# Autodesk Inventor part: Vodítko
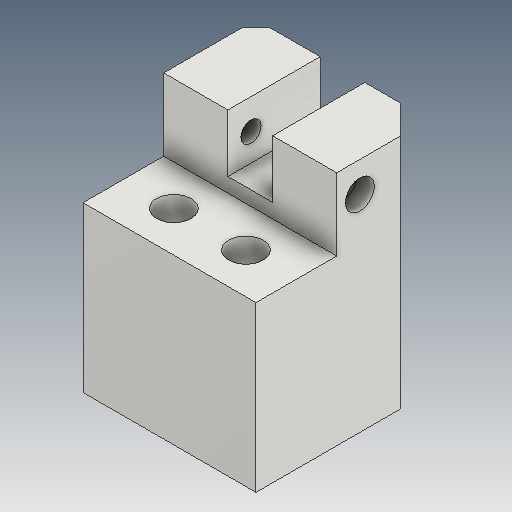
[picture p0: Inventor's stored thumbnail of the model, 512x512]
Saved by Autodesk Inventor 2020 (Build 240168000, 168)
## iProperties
Created: 2025-03
Part Number: Vodítko
Material: Ocel
Document SubType Name: Modeling
Designer: doma
Density: 7.85 g/cm^3
Appearance: Ocel
Mass: 1726.6 g
Surface Area: 323.089 cm^2
Volume: 219.949 cm^3
Author: doma
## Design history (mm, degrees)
sketch "Náčrt1"
  geometry: L1 (0, 0)-(60, 0); L2 (60, 0)-(60, 82); L3 (0, 82)-(0, 0); L4 (30, 62)-(37.75, 62); L5 (30, 62)-(22.25, 62); L6 (22.25, 62)-(22.25, 82); L7 (37.75, 62)-(37.75, 82); L8 (60, 82)-(37.75, 82); L9 (22.25, 82)-(0, 82)
  constraints: 18 end point, 3 horizontal, 3 parallel, 3 perpendicular, 1 vertical
  dimensions: "d0" = 60 distance of L3.start L2.end; "d1" = 82 distance of L2.end L1.end
extrude "Vysunutí1" new body sketch "Náčrt1" distance "d5" = 60; taper "d6" = 0 deg
sketch "Náčrt2"
  geometry: L1 (22.25, 82)-(0, 82) reference; L2 (60, 0)-(60, 82) reference; L3 (0, 82)-(60, 82); L4 (60, 82)-(60, 57); L5 (60, 57)-(0, 57); L6 (0, 57)-(0, 82); 3 further points
  constraints: 8 end point, 2 parallel, 1 horizontal, 1 perpendicular, 1 point on line
  dimensions: "d7" = 25 distance of L3.end L4.end
extrude "Vysunutí2" cut sketch "Náčrt2" distance "d8" = 28; taper "d9" = 0 deg
sketch "Náčrt3"
  geometry: L1 (0, 0)-(60, 0) reference; L2 (60, 0)-(60, 60) reference; L3 (0, 60)-(60, 60) reference; L4 (0, 0)-(0, 60) reference; L5 (0, 32)-(22.25, 32) reference; L6 (22.25, 0)-(22.25, 32) reference; L7 (37.75, 0)-(37.75, 32) reference; L8 (60, 32)-(60, 60) reference; L9 (60, 46)-(0, 46); L10 (0, 60)-(0, 32) reference; 3 further points
  constraints: 2 end point, 2 midpoint, 2 point on line, 1 horizontal
  dimensions: "d10" = 25 distance of point (17.5, 46) point (42.5, 46); "d11" = 17.5 distance from line of L4 point (17.5, 46); "d12" = 14 distance between parallel lines of L5 L9
hole "Díra1" sketch "Náčrt3" at (42.5, 46), (17.5, 46) diameter "d13" = 9; stored, may be unused: countersink angle "d17" = 90 deg, drill point angle "d19" = 118 deg; dims "d14" = 5, "d15" = 14, "d16" = 8, "d18" = 8
sketch "Náčrt4"
  geometry: C1 r 6 at (42.5, 14); C2 r 6 at (17.5, 14); 3 further points
  constraints: 2 centre point, 2 coincident
  dimensions: "d20" = 12 diameter of C1; "d21" = 12 diameter of C2
extrude "Vysunutí3" cut sketch "Náčrt4" distance "d22" = 30; taper "d23" = 0 deg
sketch "Náčrt5"
  geometry: L1 (15.5, 0)-(0, 0) reference; L2 (7.75, 0)-(7.75, -32); L3 (0, -32)-(15.5, -32) reference; C1 r 6 at (7.75, -15); 1 further point
  constraints: 2 end point, 2 midpoint, 1 centre point, 1 point on line
  dimensions: "d24" = 12 diameter of C1; "d72" = 15 distance from line of L1 C1.centre
extrude "Vysunutí4" cut sketch "Náčrt5" distance "d25" = 2; taper "d26" = 0 deg
chamfer "Zkosení1" distance "d27" = 5; stored, may be unused: second distance "d28" = 2, angle "d29" = 45 deg
sketch "Náčrt6"
  geometry: L1 (-14, 20)-(-14, 31) reference; L2 (-25, 20)-(-25, 31) reference; L3 (-38, 20)-(-38, 31) reference; L4 (-22, 31)-(-22, 20) reference; L5 (-46, 31)-(-46, 20) reference; L6 (-55, 0)-(0, 0) reference; A1 r 4 centre (-18, 20) between (-22, 20) and (-14, 20) reference; A2 r 4 centre (-18, 31) between (-14, 31) and (-22, 31) reference; A3 r 4 centre (-42, 20) between (-46, 20) and (-38, 20) reference; A4 r 4 centre (-42, 31) between (-38, 31) and (-46, 31) reference; 3 further points
  dimensions: "d33" = 25 distance from line of L6 point (-18, 25); "d34" = 25 distance from line of L6 point (-42, 25)
hole "Díra2" sketch "Náčrt6" at (-18, 25), (-42, 25) diameter "d35" = 6.647; stored, may be unused: countersink angle "d39" = 90 deg, drill point angle "d41" = 118 deg; dims "d36" = 7, "d37" = 4, "d38" = 2, "d40" = 10
sketch "Náčrt7"
  geometry: L1 (-55, 82)-(-28, 82) reference; L2 (-28, 57)-(-28, 82) reference; 2 further points
  dimensions: "d42" = 10.5 distance from line of L1 point (-36, 71.5); "d43" = 8 distance from line of L2 point (-36, 71.5)
hole "Díra3" sketch "Náčrt7" at (-36, 71.5) diameter "d44" = 7; stored, may be unused: countersink angle "d48" = 90 deg, drill point angle "d50" = 118 deg; dims "d45" = 5, "d46" = 10, "d47" = 6, "d49" = 27.45
node "Pracovní rovina1"
mirror "Zrcadlit1"
sketch "Náčrt8"
  geometry: L1 (-4, 67.5)-(-4, 75.5); L2 (0, 82)-(-32, 82) reference; L3 (0, 0)-(0, 82) reference
  constraints: 2 end point, 1 vertical
  dimensions: "d51" = 8 distance of L1.start L1.end; "d52" = 6.5 distance from line of L2 L1.end; "d53" = 4 distance from line of L3 L1.end
hole "Díra4" sketch "Náčrt8" at (-4, 75.5), (-4, 67.5) diameter "d54" = 3.242; stored, may be unused: countersink angle "d58" = 90 deg, drill point angle "d60" = 118 deg; dims "d55" = 24, "d56" = 10, "d57" = 6, "d59" = 29.8
chamfer "Zkosení3" distance "d61" = 10; stored, may be unused: second distance "d62" = 2, angle "d63" = 45 deg
sketch "Náčrt9"
  geometry: L1 (0, 0)-(60, 0) reference; L2 (30, 0)-(30, -60); L3 (37.75, -60)-(22.25, -60) reference; 2 further points
  constraints: 2 end point, 2 midpoint, 1 point on line
  dimensions: "d64" = 10 distance from line of L3 point (30, -50)
hole "Díra5" sketch "Náčrt9" at (30, -50) diameter "d65" = 8.376; stored, may be unused: countersink angle "d69" = 90 deg, drill point angle "d71" = 118 deg; dims "d66" = 10, "d67" = 10, "d68" = 6, "d70" = 55
chamfer "Zkosení4" distance "d74" = 1; stored, may be unused: second distance "d75" = 2, angle "d76" = 45 deg
sketch "Náčrt10"
  geometry: L1 (-60, 0)-(-60, 82) reference; L2 (-60, 62)-(-50, 52); L3 (-50, 82)-(-50, 0) reference; L4 (-60, 82)-(-28, 82) reference; L5 (-59, 62)-(-28, 62) reference; L6 (-60.707, 61.293)-(-50.707, 51.293); L7 (-50.707, 51.293)-(-50, 52); L8 (-60.707, 61.293)-(-60, 62)
  constraints: 8 end point, 2 parallel, 2 point on line
  dimensions: "d73" = 20 distance from line of L2.start L4; "d77" = 135 deg angle of L5 L2; "d78" = 1 distance between parallel lines of L2 L6
revolve "Rotace1" sketch "Náčrt10" stored, may be unused: angle "d79" = 90 deg
node "Těleso1"
node "Promítnutá smyčka1"
node "Referenční1"
node "Referenční2"
node "Referenční3"
node "Referenční4"
node "Referenční5"
node "Referenční6"
node "Referenční7"
node "Referenční8"
node "Referenční9"
